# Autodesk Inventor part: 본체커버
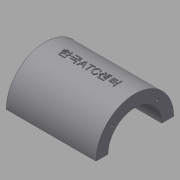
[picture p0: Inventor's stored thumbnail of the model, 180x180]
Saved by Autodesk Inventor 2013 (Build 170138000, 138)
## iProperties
Created: 2015-12
Part Number: 본체커버
Material: 알루미늄 6061
Document SubType Name: Modeling
Designer: mduedu
Density: 2.71 g/cm^3
Mass: 199.348 g
Surface Area: 200.806 cm^2
Volume: 73.5601 cm^3
Author: mduedu
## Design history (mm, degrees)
sketch "스케치1"
  geometry: L1 (45, 40)-(-45, 40); L2 (-45, 40)-(-45, -40); L3 (-45, -40)-(45, -40); L4 (45, -40)-(45, 40); L5 (45, 40)-(-45, -40); L6 (-45, 40)-(45, -40); 1 further point
  constraints: 12 end point, 2 midpoint, 2 parallel, 1 horizontal, 1 perpendicular
  dimensions: "d0" = 90 distance of L2.end L3.end; "d2" = 80 distance of L1.end L2.end
extrude "돌출1" new body sketch "스케치1" distance "d3" = 10; taper "d4" = 0 deg
sketch "스케치2"
  geometry: L1 (0, 40)-(0, -40) reference; C1 r 32.5 at (80, 0); 1 further point
  constraints: 1 centre point
  dimensions: "d5" = 65 diameter of C1; "d6" = 80 distance from line of C1.centre L1
extrude "돌출2" join sketch "스케치2" stored distance "d7" = 75; taper "d8" = 0 deg
sketch "스케치3"
  geometry: L1 (-27.5, -20)-(27.5, -20); L2 (27.5, -20)-(27.5, 20); L3 (27.5, 20)-(-27.5, 20); L4 (-27.5, 20)-(-27.5, -20); L5 (-27.5, -20)-(27.5, 20); L6 (27.5, -20)-(-27.5, 20); 1 further point
  constraints: 12 end point, 2 midpoint, 2 parallel, 1 horizontal, 1 perpendicular
  dimensions: "d9" = 55 distance of L2.end L3.end; "d11" = 40 distance of L1.end L2.end
extrude "돌출3" new body sketch "스케치3" stored distance "d12" = 75; taper "d13" = 0 deg
fillet "모깎기1"
fillet "모깎기2"
feature "결합1"
  node "솔리드2"
fillet "모깎기3" dims "d14" = 10
sketch "스케치4"
  geometry: L1 (-37.5, 47.5)-(37.5, 47.5) reference; L2 (35, 10)-(45, 10) reference; L3 (32.5, 47.5)-(40, 10); L4 (37.5, 47.5)-(37.5, 112.5) reference; L5 (45, 10)-(45, 0) reference; 1 further point
  constraints: 2 end point, 1 midpoint, 1 point on line
  dimensions: "d15" = 5 distance from line of L3.start L4; "d16" = 5 distance from line of L3.end L5
sketch "스케치5"
  geometry: L1 (10, 40)-(10, 30) reference; L2 (10, 35)-(56.569, 22.522); L3 (0, 40)-(10, 40) reference; 2 further points
  constraints: 2 end point, 1 midpoint, 2 other
  dimensions: "d17" = 5 distance from line of L2.start L3; "d18" = 15 deg angle of L2 L3
feature "리브1" dims "d19" = 1, "d20" = 6, "d21" = 0, "d22" = 0, "d23" = 1, "d24" = 1
feature "리브2" dims "d25" = 1, "d26" = 6, "d27" = 0, "d28" = 0, "d29" = 1, "d30" = 1
fillet "모깎기4" dims "d31" = 2
fillet "모깎기5" dims "d32" = 2
fillet "모깎기6" dims "d33" = 2
sketch "스케치6"
  geometry: A1 r 10 centre (-35, 30) between (-35, 40) and (-45, 30) reference; A2 r 10 centre (35, 30) between (45, 30) and (35, 40) reference; A3 r 10 centre (35, -30) between (35, -40) and (45, -30) reference; A4 r 10 centre (-35, -30) between (-45, -30) and (-35, -40) reference; 5 further points
  constraints: 4 coincident
hole "구멍1" sketch "스케치6" at (-35, 30), (35, 30), (35, -30), (-35, -30) diameter "d34" = 7; stored, may be unused: countersink angle "d38" = 90 deg, drill point angle "d40" = 118 deg; dims "d35" = 6, "d36" = 12, "d37" = 3, "d39" = 8
fillet "모깎기7" dims "d41" = 2
hole "구멍2" diameter "d44" = 45; stored, may be unused: countersink angle "d48" = 90 deg, drill point angle "d50" = 118 deg; dims "d42" = 10, "d43" = 10, "d45" = 6, "d46" = 4, "d47" = 2, "d49" = 8
sketch "스케치7" dims "d52" = 26.5
  geometry: L1 (0, 0)-(32.5, 0); L2 (0, 0)-(22.981, 22.981); A1 r 32.5 centre (0, 0) between (32.5, 0) and (22.981, 22.981) reference; 3 further points
  constraints: 4 end point, 2 point on circle, 1 coincident, 1 horizontal, 1 point on line, 3 other
  dimensions: "d51" = 45 deg angle of L2 L1
hole "구멍3" sketch "스케치7" at (18.738, 18.738) diameter "d54" = 2.459; stored, may be unused: countersink angle "d58" = 90 deg, drill point angle "d60" = 118 deg; dims "d55" = 8, "d56" = 4, "d57" = 2, "d59" = 10
sketch "스케치13"
  geometry: L1 (-45, 80)-(105, 80); L2 (105, 80)-(105, -30); L3 (105, -30)-(-45, -30); L4 (-45, -30)-(-45, 80); L5 (0, 0)-(60, 0) reference; C1 r 32.5 at (30, 80) reference; 1 further point
  constraints: 8 end point, 2 parallel, 1 coincident, 1 horizontal, 1 midpoint, 1 perpendicular
  dimensions: "d99" = 30 distance between parallel lines of L3 L5; "d126" = 150 distance between parallel lines of L2 L4
extrude "돌출8" cut sketch "스케치13" stored distance "d97" = 10; taper "d98" = 0 deg
node "작업 평면2"
sketch "스케치14"
  geometry: 2 further points
  constraints: 1 coincident, 1 other
feature "엠보싱1" sketch "스케치14" dims "d102" = 0.5, "d103" = 0
sketch "스케치18"
  geometry: L1 (0, -10)-(0, 0) reference; L2 (75, 0)-(75, -10) reference; L3 (0, -5)-(75, -5); C1 r 1.5 at (13, -5); 1 further point
  constraints: 2 end point, 2 midpoint, 1 centre point, 1 point on line
  dimensions: "d127" = 3 diameter of C1; "d128" = 13 distance from line of L1 C1.centre
extrude "돌출9" cut sketch "스케치18" distance "d129" = 2; taper "d130" = 0 deg
chamfer "모따기2" distance "d131" = 0.5; stored, may be unused: second distance "d132" = 2, angle "d133" = 45 deg
fillet "모깎기12" dims "d134" = 0.1
node "솔리드1"
mirror "대칭1"
mirror "대칭2"
pattern_circular "원형 패턴1" dims angle "d62" = 360 deg
mirror "대칭3"
mirror "대칭5"
mirror "대칭6"
